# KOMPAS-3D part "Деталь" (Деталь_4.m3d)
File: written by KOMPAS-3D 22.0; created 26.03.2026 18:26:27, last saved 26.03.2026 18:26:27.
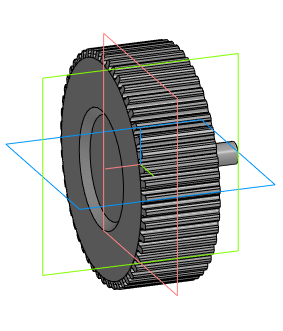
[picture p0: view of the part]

Document properties: Автор: Пользователь Windows; Полное имя файла: F:\Танк\Деталь_4.m3d

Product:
- Part/product: Деталь

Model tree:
1. Операция без истории:1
